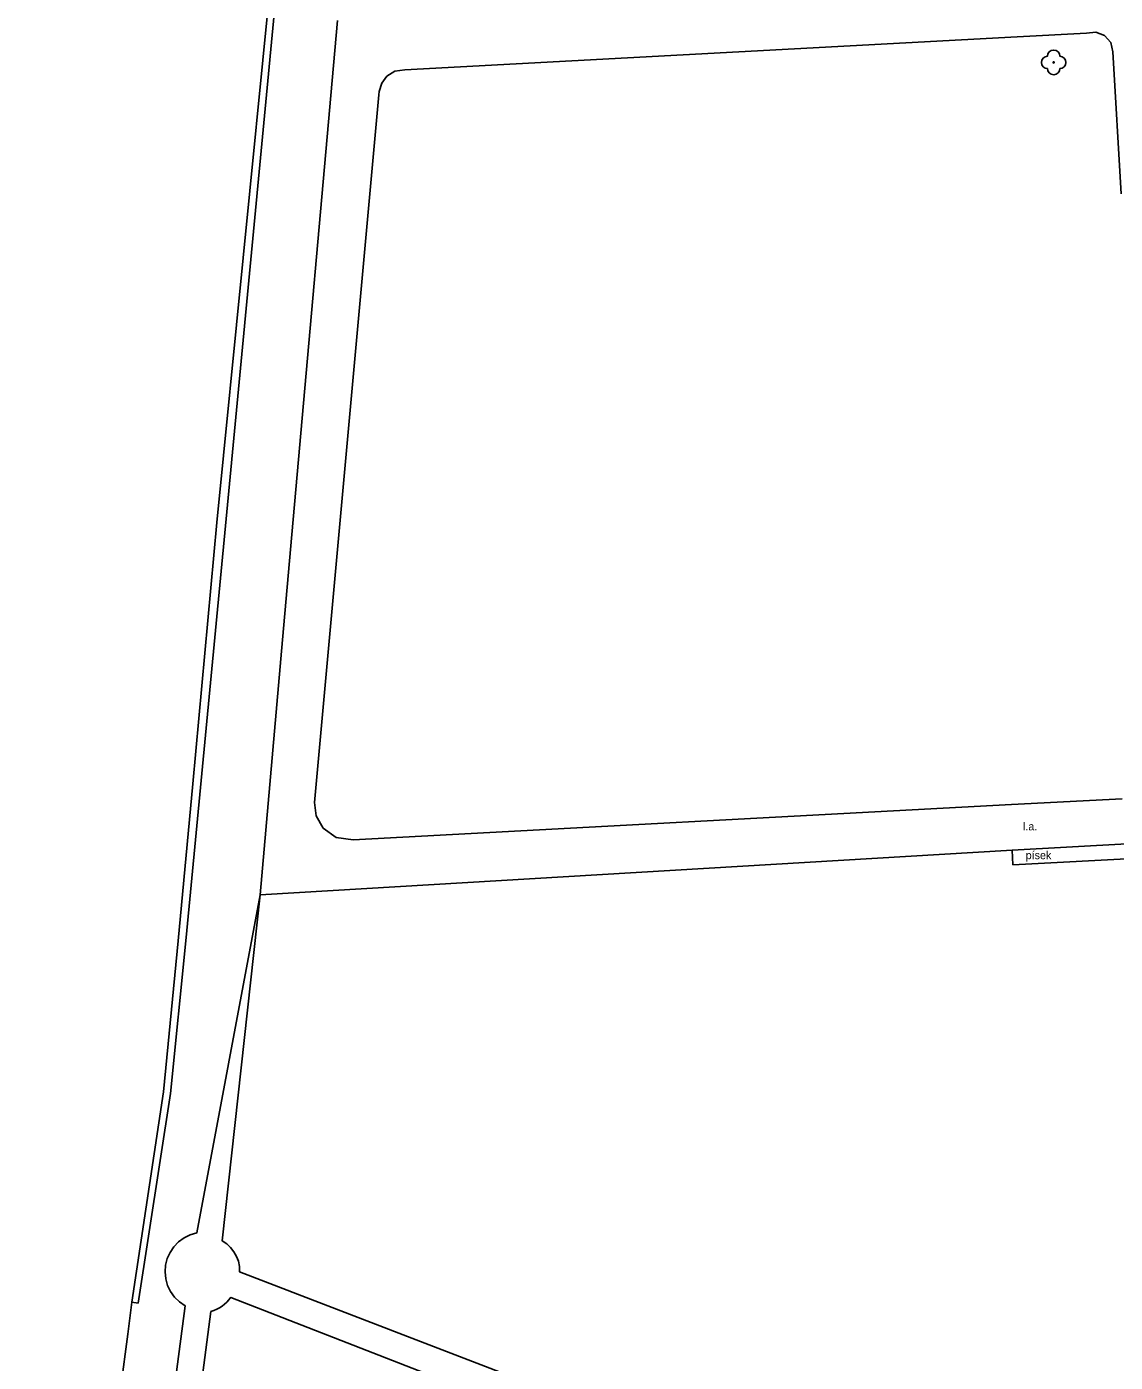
# Model space of a CAD drawing. Extents: x -599951 to -598963, y -1164095 to -1162939.
# Drawn here: x -599750.3 to -599661.9, y -1163692.1 to -1163583.6 of the extents above; entities that cross this region are included whole.
import ezdxf

# ---------------------------------------------------------------- set-up
doc = ezdxf.new("R2010")
doc.units = 0
for name, color, linetype in [('Level 11', 7, 'Continuous'), ('Level 22', 7, 'Continuous'), ('Level 40', 7, 'Continuous'), ('Level 51', 7, 'Continuous'), ('Level 54', 7, 'Continuous')]:
    doc.layers.add(name, color=color, linetype=linetype)

msp = doc.modelspace()

# ---------------------------------------------------------------- linework, layer by layer
at = {"layer": 'Level 11'}
for points in [[(-599664.26, -1163584.09), (-599663.5, -1163584), (-599662.79, -1163584.28), (-599662.29, -1163584.85)], [(-599664.26, -1163584.09), (-599669.88, -1163584.4)], [(-599662.29, -1163584.85), (-599662.12, -1163585.6)], [(-599661.45, -1163597.14), (-599662.12, -1163585.6)], [(-599670.35, -1163646.75), (-599661.35, -1163646.28)], [(-599660.97, -1163649.94), (-599670.3, -1163650.46)], [(-599670.3, -1163650.46), (-599670.24, -1163651.64)], [(-599659.46, -1163651.09), (-599670.24, -1163651.64)], [(-599750.32, -1163785.31), (-599737.46, -1163687.46), (-599737.92, -1163687.15), (-599738.31, -1163686.76), (-599738.64, -1163686.31), (-599738.88, -1163685.81), (-599739.03, -1163685.27), (-599739.08, -1163684.72), (-599739.04, -1163684.17), (-599738.91, -1163683.63), (-599738.68, -1163683.13), (-599738.37, -1163682.67), (-599737.99, -1163682.27), (-599737.54, -1163681.94), (-599737.04, -1163681.69), (-599736.51, -1163681.54), (-599731.35, -1163654.08)], [(-599667.2, -1163710.04), (-599733.03, -1163684.71), (-599733.05, -1163684.28), (-599733.13, -1163683.85), (-599733.28, -1163683.45), (-599733.49, -1163683.07), (-599733.76, -1163682.73), (-599734.08, -1163682.44), (-599734.44, -1163682.2), (-599731.35, -1163654.08)], [(-599733.75, -1163686.78), (-599698.03, -1163700.71)], [(-599739.2, -1163717.38), (-599735.36, -1163687.94)]]:
    msp.add_lwpolyline(points, dxfattribs=at)
msp.add_arc((-599736.33, -1163684.89), 3.2, 287.698, 323.8473, dxfattribs=at)
at = {"layer": 'Level 22'}
msp.add_circle((-599666.92, -1163586.47), 0.05, dxfattribs=at)
for centre, start, end in [((-599667.42, -1163586.47), 90, 270), ((-599666.92, -1163585.97), 0, 180), ((-599666.42, -1163586.47), 270, 90), ((-599666.92, -1163586.97), 180, 0)]:
    msp.add_arc(centre, 0.5, start, end, dxfattribs=at)
at = {"layer": 'Level 51'}
for points in [[(-599742.11, -1163689.78), (-599741.78, -1163687.17)], [(-599742.11, -1163689.78), (-599741.78, -1163687.17)], [(-599743.81, -1163702.61), (-599742.11, -1163689.78)], [(-599743.81, -1163702.61), (-599742.11, -1163689.78)]]:
    msp.add_lwpolyline(points, dxfattribs=at)
at = {"layer": 'Level 54'}
for points in [[(-599730.61, -1163580.81), (-599734.88, -1163623.85)], [(-599730.61, -1163580.81), (-599734.88, -1163623.85)], [(-599730.06, -1163580.82), (-599734.18, -1163624.1)], [(-599728.79, -1163624.82), (-599725.09, -1163583.06)], [(-599719.6, -1163587.07), (-599669.88, -1163584.4)], [(-599721.08, -1163587.6), (-599720.43, -1163587.19)], [(-599720.43, -1163587.19), (-599719.6, -1163587.07)], [(-599721.71, -1163588.82), (-599721.48, -1163588.15)], [(-599721.48, -1163588.15), (-599721.08, -1163587.6)], [(-599726.94, -1163646.58), (-599721.73, -1163589.09)], [(-599721.73, -1163589.09), (-599721.71, -1163588.82)], [(-599734.18, -1163624.1), (-599737.38, -1163657.54)], [(-599734.88, -1163623.85), (-599736.82, -1163645.08)], [(-599734.88, -1163623.85), (-599736.82, -1163645.08)], [(-599731.35, -1163654.08), (-599729.54, -1163633.38), (-599728.79, -1163624.82)], [(-599736.82, -1163645.08), (-599738.01, -1163657.82)], [(-599726.81, -1163647.67), (-599726.94, -1163646.58)], [(-599670.35, -1163646.75), (-599723.82, -1163649.61)], [(-599726.24, -1163648.67), (-599726.81, -1163647.67)], [(-599725.18, -1163649.42), (-599726.24, -1163648.67)], [(-599723.82, -1163649.61), (-599725.18, -1163649.42)], [(-599670.3, -1163650.46), (-599731.35, -1163654.08)], [(-599738.01, -1163657.82), (-599739.22, -1163670.08)], [(-599737.38, -1163657.54), (-599738.63, -1163670.22)], [(-599739.22, -1163670.08), (-599741.78, -1163687.17)], [(-599739.22, -1163670.08), (-599741.78, -1163687.17)], [(-599738.63, -1163670.22), (-599741.26, -1163687.25)], [(-599741.26, -1163687.25), (-599741.78, -1163687.17)], [(-599741.26, -1163687.25), (-599741.78, -1163687.17)]]:
    msp.add_lwpolyline(points, dxfattribs=at)

# ---------------------------------------------------------------- texts
at = {"layer": 'Level 40'}
for s, p in [('l.a.', (-599669.41, -1163648.85)), ('písek', (-599669.19, -1163651.19))]:
    msp.add_text(s, height=0.65, dxfattribs=at).set_placement(p)

doc.saveas('drawing.dxf')
